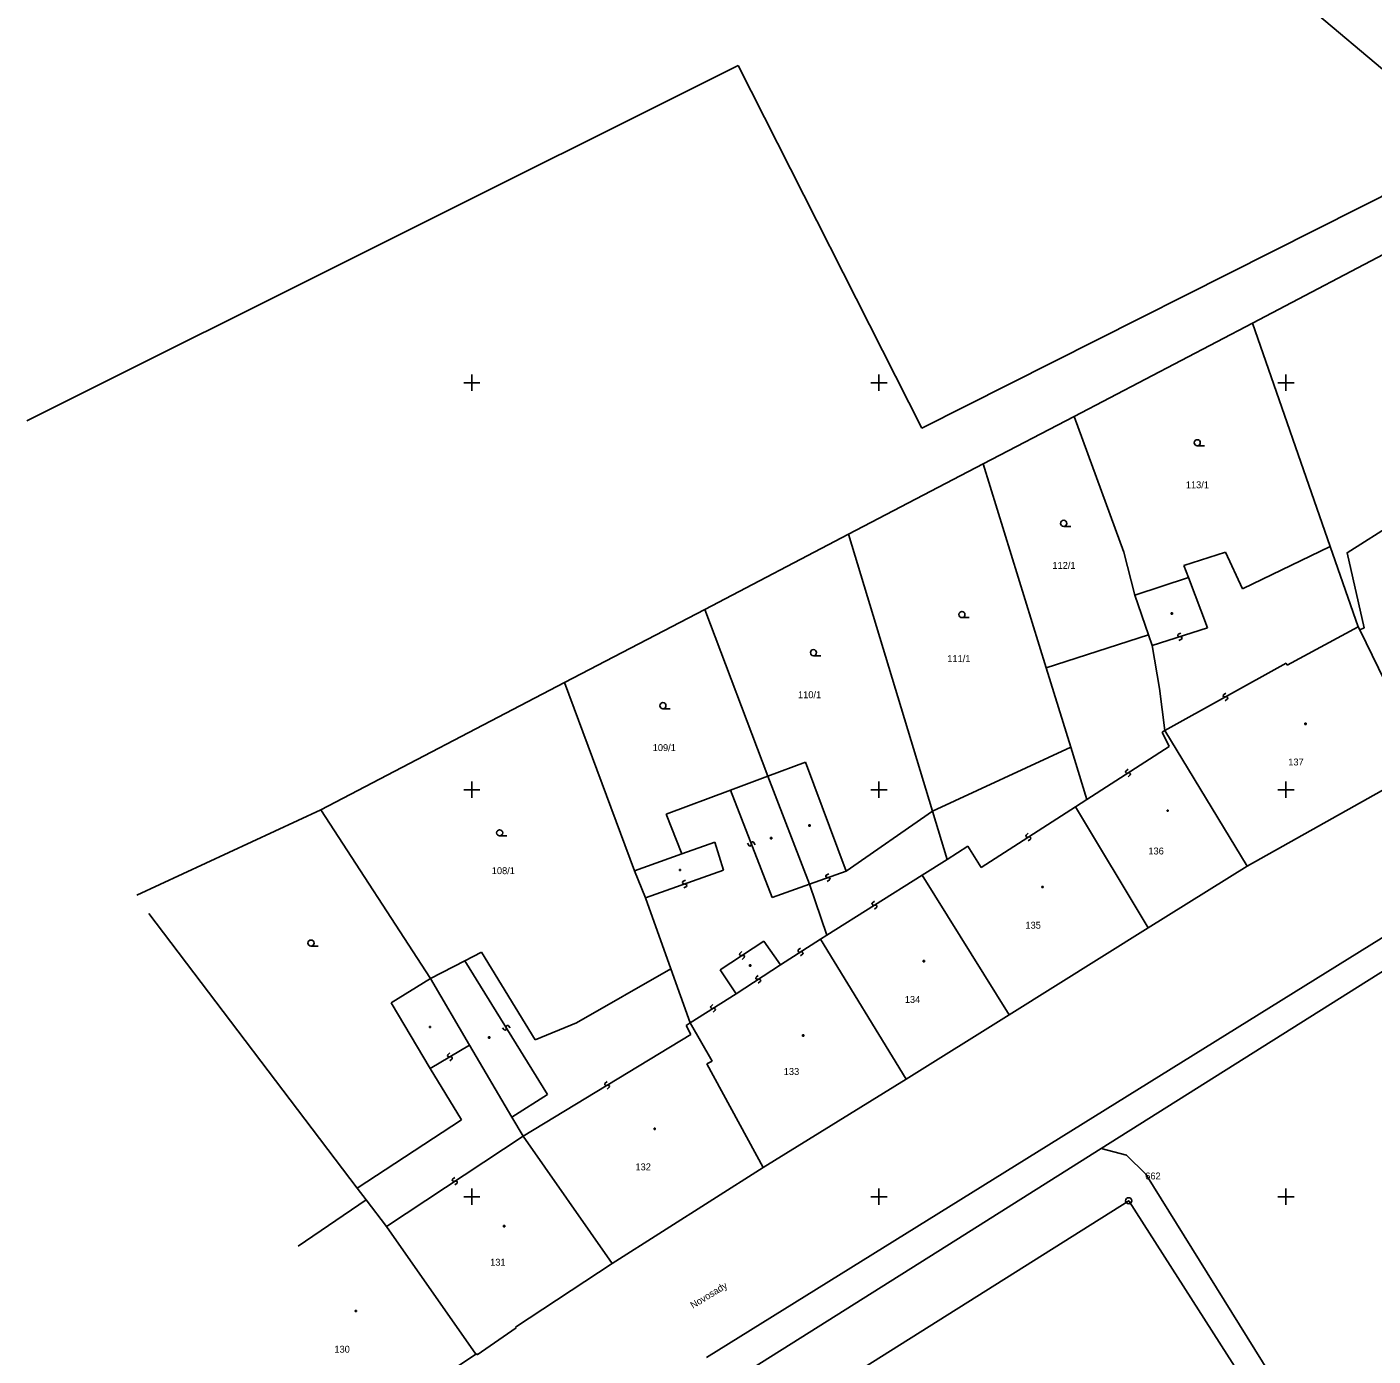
# Model space of a CAD drawing. Extents: x -492379 to -491966, y -1126153 to -1125860.
# Drawn here: x -492332.8 to -492233.6, y -1126091.7 to -1125993.8 of the extents above; entities that cross this region are included whole.
import ezdxf

# ---------------------------------------------------------------- set-up
doc = ezdxf.new("R2010")
doc.units = 0
doc.layers.add('katastrální mapa', color=7, linetype='Continuous')
doc.layers.add('síť', color=7, linetype='Continuous')

msp = doc.modelspace()

# ---------------------------------------------------------------- linework, layer by layer
at = {"layer": 'katastrální mapa'}
for p, q in [((-492225.94, -1126002.74), (-492307.13, -1125934.3)), ((-492332.79, -1126022.8), (-492280.36, -1125996.63)), ((-492280.36, -1125996.63), (-492266.84, -1126023.35)), ((-492266.84, -1126023.35), (-492225.94, -1126002.74)), ((-492242.46, -1126015.61), (-492228.24, -1126008.13)), ((-492255.61, -1126022.48), (-492242.46, -1126015.61)), ((-492242.46, -1126015.61), (-492236.73, -1126032.07)), ((-492262.32, -1126025.98), (-492255.61, -1126022.48)), ((-492255.61, -1126022.48), (-492251.95, -1126032.5)), ((-492246.54, -1126024.65), (-492246.01, -1126024.65)), ((-492272.25, -1126031.17), (-492262.32, -1126025.98)), ((-492262.32, -1126025.98), (-492257.67, -1126041.01)), ((-492282.84, -1126036.71), (-492272.25, -1126031.17)), ((-492272.25, -1126031.17), (-492266.05, -1126051.59)), ((-492256.38, -1126030.59), (-492255.85, -1126030.59)), ((-492243.2, -1126035.19), (-492236.73, -1126032.07)), ((-492236.73, -1126032.07), (-492234.67, -1126037.99)), ((-492251.95, -1126032.5), (-492251.14, -1126035.67)), ((-492247.52, -1126033.47), (-492244.45, -1126032.49)), ((-492244.45, -1126032.49), (-492243.2, -1126035.19)), ((-492251.14, -1126035.67), (-492247.18, -1126034.35)), ((-492247.52, -1126033.47), (-492247.18, -1126034.35)), ((-492247.18, -1126034.35), (-492245.78, -1126038.07)), ((-492251.14, -1126035.67), (-492250.14, -1126038.58)), ((-492293.17, -1126042.1), (-492282.84, -1126036.71)), ((-492282.84, -1126036.71), (-492278.18, -1126049.01)), ((-492263.88, -1126037.31), (-492263.35, -1126037.31)), ((-492248.45, -1126036.97), (-492248.36, -1126036.97)), ((-492248.45, -1126037.06), (-492248.45, -1126036.97)), ((-492248.36, -1126037.06), (-492248.45, -1126037.06)), ((-492248.36, -1126036.97), (-492248.36, -1126037.06)), ((-492249.86, -1126039.38), (-492245.78, -1126038.07)), ((-492239.9, -1126040.81), (-492234.67, -1126037.99)), ((-492234.67, -1126037.99), (-492234.56, -1126038.22)), ((-492234.56, -1126038.22), (-492230.32, -1126046.95)), ((-492257.67, -1126041.01), (-492250.14, -1126038.58)), ((-492250.14, -1126038.58), (-492249.86, -1126039.38)), ((-492249.86, -1126039.38), (-492249.31, -1126042.54)), ((-492247.94, -1126038.54), (-492247.98, -1126038.62)), ((-492247.98, -1126038.62), (-492247.96, -1126038.68)), ((-492247.96, -1126038.68), (-492247.89, -1126038.71)), ((-492247.75, -1126038.45), (-492247.94, -1126038.54)), ((-492247.89, -1126038.71), (-492247.75, -1126038.74)), ((-492247.7, -1126038.91), (-492247.89, -1126039)), ((-492247.75, -1126038.74), (-492247.68, -1126038.77)), ((-492247.66, -1126038.83), (-492247.7, -1126038.91)), ((-492247.68, -1126038.77), (-492247.66, -1126038.83)), ((-492274.82, -1126040.12), (-492274.29, -1126040.12)), ((-492257.67, -1126041.01), (-492255.86, -1126046.86)), ((-492248.92, -1126045.64), (-492239.99, -1126040.68)), ((-492239.99, -1126040.68), (-492239.9, -1126040.81)), ((-492311.14, -1126051.49), (-492293.17, -1126042.1)), ((-492293.17, -1126042.1), (-492288.01, -1126055.97)), ((-492249.31, -1126042.54), (-492248.92, -1126045.64)), ((-492244.61, -1126043.01), (-492244.63, -1126043.09)), ((-492244.63, -1126043.09), (-492244.6, -1126043.14)), ((-492244.44, -1126042.88), (-492244.61, -1126043.01)), ((-492244.6, -1126043.14), (-492244.52, -1126043.16)), ((-492244.52, -1126043.16), (-492244.39, -1126043.16)), ((-492244.3, -1126043.31), (-492244.47, -1126043.44)), ((-492244.39, -1126043.16), (-492244.31, -1126043.18)), ((-492244.31, -1126043.18), (-492244.28, -1126043.23)), ((-492244.28, -1126043.23), (-492244.3, -1126043.31)), ((-492285.92, -1126044.03), (-492285.39, -1126044.03)), ((-492238.6, -1126045.09), (-492238.51, -1126045.09)), ((-492238.6, -1126045.18), (-492238.6, -1126045.09)), ((-492238.51, -1126045.18), (-492238.6, -1126045.18)), ((-492238.51, -1126045.09), (-492238.51, -1126045.18)), ((-492249.13, -1126045.75), (-492248.92, -1126045.64)), ((-492249.13, -1126045.75), (-492248.61, -1126046.82)), ((-492248.92, -1126045.64), (-492242.87, -1126055.62)), ((-492266.05, -1126051.59), (-492255.86, -1126046.86)), ((-492255.86, -1126046.86), (-492254.67, -1126050.71)), ((-492254.67, -1126050.71), (-492248.61, -1126046.82)), ((-492278.18, -1126049.01), (-492275.42, -1126047.97)), ((-492275.42, -1126047.97), (-492272.4, -1126055.99)), ((-492242.87, -1126055.62), (-492229.69, -1126048.25)), ((-492280.94, -1126050.04), (-492278.18, -1126049.01)), ((-492278.18, -1126049.01), (-492275.11, -1126056.96)), ((-492251.8, -1126048.62), (-492251.82, -1126048.7)), ((-492251.82, -1126048.7), (-492251.79, -1126048.75)), ((-492251.64, -1126048.48), (-492251.8, -1126048.62)), ((-492251.79, -1126048.75), (-492251.71, -1126048.77)), ((-492251.71, -1126048.77), (-492251.57, -1126048.76)), ((-492251.48, -1126048.91), (-492251.64, -1126049.05)), ((-492251.57, -1126048.76), (-492251.49, -1126048.78)), ((-492251.49, -1126048.78), (-492251.46, -1126048.83)), ((-492251.46, -1126048.83), (-492251.48, -1126048.91)), ((-492285.68, -1126051.81), (-492280.94, -1126050.04)), ((-492280.94, -1126050.04), (-492277.86, -1126057.95)), ((-492262.47, -1126055.72), (-492255.51, -1126051.25)), ((-492255.51, -1126051.25), (-492254.67, -1126050.71)), ((-492255.51, -1126051.25), (-492250.16, -1126060.18)), ((-492324.68, -1126057.78), (-492311.14, -1126051.49)), ((-492311.14, -1126051.49), (-492303.04, -1126063.92)), ((-492285.68, -1126051.81), (-492284.53, -1126054.73)), ((-492272.4, -1126055.99), (-492266.05, -1126051.59)), ((-492266.05, -1126051.59), (-492264.98, -1126055.13)), ((-492248.76, -1126051.5), (-492248.67, -1126051.5)), ((-492248.76, -1126051.59), (-492248.76, -1126051.5)), ((-492248.67, -1126051.59), (-492248.76, -1126051.59)), ((-492248.67, -1126051.5), (-492248.67, -1126051.59)), ((-492275.16, -1126052.59), (-492275.07, -1126052.59)), ((-492275.16, -1126052.68), (-492275.16, -1126052.59)), ((-492275.07, -1126052.68), (-492275.16, -1126052.68)), ((-492275.07, -1126052.59), (-492275.07, -1126052.68)), ((-492258.99, -1126053.2), (-492259.15, -1126053.34)), ((-492297.95, -1126053.4), (-492297.42, -1126053.4)), ((-492284.53, -1126054.73), (-492282.1, -1126053.86)), ((-492282.1, -1126053.86), (-492281.44, -1126055.92)), ((-492279.57, -1126054.13), (-492279.68, -1126053.94)), ((-492279.5, -1126054.16), (-492279.57, -1126054.13)), ((-492279.44, -1126054.14), (-492279.5, -1126054.16)), ((-492279.41, -1126054.06), (-492279.44, -1126054.14)), ((-492279.39, -1126053.93), (-492279.41, -1126054.06)), ((-492279.36, -1126053.85), (-492279.39, -1126053.93)), ((-492279.3, -1126053.83), (-492279.36, -1126053.85)), ((-492279.23, -1126053.86), (-492279.3, -1126053.83)), ((-492279.12, -1126054.05), (-492279.23, -1126053.86)), ((-492277.98, -1126053.53), (-492277.89, -1126053.53)), ((-492277.98, -1126053.62), (-492277.98, -1126053.53)), ((-492277.89, -1126053.62), (-492277.98, -1126053.62)), ((-492277.89, -1126053.53), (-492277.89, -1126053.62)), ((-492264.98, -1126055.13), (-492263.45, -1126054.17)), ((-492263.45, -1126054.17), (-492262.47, -1126055.72)), ((-492259.15, -1126053.34), (-492259.17, -1126053.42)), ((-492259.17, -1126053.42), (-492259.14, -1126053.47)), ((-492259.14, -1126053.47), (-492259.06, -1126053.49)), ((-492259.06, -1126053.49), (-492258.92, -1126053.48)), ((-492258.83, -1126053.63), (-492258.99, -1126053.77)), ((-492258.92, -1126053.48), (-492258.84, -1126053.5)), ((-492258.84, -1126053.5), (-492258.81, -1126053.55)), ((-492258.81, -1126053.55), (-492258.83, -1126053.63)), ((-492288.01, -1126055.97), (-492284.53, -1126054.73)), ((-492266.81, -1126056.29), (-492264.98, -1126055.13)), ((-492288.01, -1126055.97), (-492287.2, -1126057.97)), ((-492287.2, -1126057.97), (-492281.44, -1126055.92)), ((-492284.7, -1126055.87), (-492284.61, -1126055.87)), ((-492284.7, -1126055.96), (-492284.7, -1126055.87)), ((-492284.61, -1126055.96), (-492284.7, -1126055.96)), ((-492284.61, -1126055.87), (-492284.61, -1126055.96)), ((-492275.11, -1126056.96), (-492272.4, -1126055.99)), ((-492273.69, -1126056.2), (-492273.88, -1126056.3)), ((-492250.16, -1126060.18), (-492242.87, -1126055.62)), ((-492284.45, -1126056.77), (-492284.48, -1126056.84)), ((-492284.48, -1126056.84), (-492284.46, -1126056.9)), ((-492284.46, -1126056.9), (-492284.39, -1126056.94)), ((-492284.26, -1126056.67), (-492284.45, -1126056.77)), ((-492284.39, -1126056.94), (-492284.25, -1126056.95)), ((-492284.19, -1126057.12), (-492284.38, -1126057.22)), ((-492284.25, -1126056.95), (-492284.18, -1126056.99)), ((-492284.16, -1126057.05), (-492284.19, -1126057.12)), ((-492284.18, -1126056.99), (-492284.16, -1126057.05)), ((-492282.7, -1126091.84), (-492226.15, -1126056.69)), ((-492277.86, -1126057.95), (-492275.11, -1126056.96)), ((-492275.11, -1126056.96), (-492273.84, -1126060.72)), ((-492273.88, -1126056.3), (-492273.92, -1126056.37)), ((-492273.92, -1126056.37), (-492273.9, -1126056.43)), ((-492273.9, -1126056.43), (-492273.82, -1126056.47)), ((-492273.84, -1126060.72), (-492266.81, -1126056.29)), ((-492273.82, -1126056.47), (-492273.69, -1126056.48)), ((-492273.63, -1126056.65), (-492273.82, -1126056.75)), ((-492273.69, -1126056.48), (-492273.61, -1126056.52)), ((-492273.59, -1126056.58), (-492273.63, -1126056.65)), ((-492273.61, -1126056.52), (-492273.59, -1126056.58)), ((-492266.81, -1126056.29), (-492260.41, -1126066.58)), ((-492257.98, -1126057.12), (-492257.89, -1126057.12)), ((-492257.98, -1126057.21), (-492257.98, -1126057.12)), ((-492257.89, -1126057.21), (-492257.98, -1126057.21)), ((-492257.89, -1126057.12), (-492257.89, -1126057.21)), ((-492287.2, -1126057.97), (-492285.34, -1126063.2)), ((-492270.33, -1126058.22), (-492270.49, -1126058.36)), ((-492323.81, -1126059.12), (-492308.44, -1126079.36)), ((-492270.49, -1126058.36), (-492270.51, -1126058.44)), ((-492270.51, -1126058.44), (-492270.47, -1126058.49)), ((-492270.47, -1126058.49), (-492270.39, -1126058.51)), ((-492270.39, -1126058.51), (-492270.26, -1126058.5)), ((-492270.16, -1126058.65), (-492270.32, -1126058.79)), ((-492270.26, -1126058.5), (-492270.18, -1126058.52)), ((-492270.18, -1126058.52), (-492270.14, -1126058.57)), ((-492270.14, -1126058.57), (-492270.16, -1126058.65)), ((-492260.41, -1126066.58), (-492250.16, -1126060.18)), ((-492281.69, -1126063.28), (-492278.48, -1126061.15)), ((-492278.48, -1126061.15), (-492277.25, -1126062.9)), ((-492277.25, -1126062.9), (-492274.3, -1126061.01)), ((-492274.3, -1126061.01), (-492273.84, -1126060.72)), ((-492274.3, -1126061.01), (-492268, -1126071.33)), ((-492311.85, -1126061.53), (-492311.32, -1126061.53)), ((-492300.51, -1126062.61), (-492299.29, -1126061.97)), ((-492299.29, -1126061.97), (-492295.33, -1126068.44)), ((-492280.25, -1126062.07), (-492280.27, -1126062.16)), ((-492280.27, -1126062.16), (-492280.23, -1126062.21)), ((-492280.09, -1126061.93), (-492280.25, -1126062.07)), ((-492280.23, -1126062.21), (-492280.15, -1126062.22)), ((-492280.15, -1126062.22), (-492280.02, -1126062.21)), ((-492280.02, -1126062.21), (-492279.94, -1126062.22)), ((-492279.94, -1126062.22), (-492279.9, -1126062.27)), ((-492275.94, -1126061.81), (-492275.96, -1126061.89)), ((-492275.96, -1126061.89), (-492275.92, -1126061.94)), ((-492275.78, -1126061.67), (-492275.94, -1126061.81)), ((-492275.92, -1126061.94), (-492275.84, -1126061.96)), ((-492275.84, -1126061.96), (-492275.71, -1126061.95)), ((-492275.61, -1126062.1), (-492275.77, -1126062.24)), ((-492275.71, -1126061.95), (-492275.63, -1126061.97)), ((-492275.63, -1126061.97), (-492275.59, -1126062.02)), ((-492275.59, -1126062.02), (-492275.61, -1126062.1)), ((-492303.04, -1126063.92), (-492300.51, -1126062.61)), ((-492300.51, -1126062.61), (-492294.42, -1126072.47)), ((-492292.29, -1126067.18), (-492285.34, -1126063.2)), ((-492285.34, -1126063.2), (-492283.92, -1126067.19)), ((-492280.53, -1126065.03), (-492277.25, -1126062.9)), ((-492279.92, -1126062.36), (-492280.08, -1126062.5)), ((-492279.9, -1126062.27), (-492279.92, -1126062.36)), ((-492279.54, -1126062.91), (-492279.45, -1126062.91)), ((-492279.54, -1126063), (-492279.54, -1126062.91)), ((-492279.45, -1126063), (-492279.54, -1126063)), ((-492279.45, -1126062.91), (-492279.45, -1126063)), ((-492266.73, -1126062.59), (-492266.64, -1126062.59)), ((-492266.73, -1126062.68), (-492266.73, -1126062.59)), ((-492266.64, -1126062.68), (-492266.73, -1126062.68)), ((-492266.64, -1126062.59), (-492266.64, -1126062.68)), ((-492253.63, -1126076.45), (-492231.88, -1126062.75)), ((-492305.94, -1126065.7), (-492303.04, -1126063.92)), ((-492303.04, -1126063.92), (-492300.16, -1126068.83)), ((-492281.69, -1126063.28), (-492280.53, -1126065.03)), ((-492279.05, -1126063.82), (-492279.07, -1126063.9)), ((-492279.07, -1126063.9), (-492279.04, -1126063.95)), ((-492278.89, -1126063.68), (-492279.05, -1126063.82)), ((-492279.04, -1126063.95), (-492278.96, -1126063.97)), ((-492278.96, -1126063.97), (-492278.82, -1126063.96)), ((-492278.73, -1126064.11), (-492278.89, -1126064.25)), ((-492278.82, -1126063.96), (-492278.74, -1126063.98)), ((-492278.74, -1126063.98), (-492278.71, -1126064.03)), ((-492278.71, -1126064.03), (-492278.73, -1126064.11)), ((-492283.92, -1126067.19), (-492280.53, -1126065.03)), ((-492305.94, -1126065.7), (-492303.07, -1126070.54)), ((-492282.39, -1126065.97), (-492282.41, -1126066.05)), ((-492282.41, -1126066.05), (-492282.37, -1126066.1)), ((-492282.23, -1126065.83), (-492282.39, -1126065.97)), ((-492282.37, -1126066.1), (-492282.29, -1126066.12)), ((-492282.29, -1126066.12), (-492282.16, -1126066.1)), ((-492282.16, -1126066.1), (-492282.08, -1126066.12)), ((-492282.08, -1126066.12), (-492282.04, -1126066.17)), ((-492282.04, -1126066.17), (-492282.06, -1126066.25)), ((-492295.33, -1126068.44), (-492292.29, -1126067.18)), ((-492282.06, -1126066.25), (-492282.22, -1126066.39)), ((-492268, -1126071.33), (-492260.41, -1126066.58)), ((-492303.13, -1126067.44), (-492303.04, -1126067.44)), ((-492303.13, -1126067.53), (-492303.13, -1126067.44)), ((-492303.04, -1126067.53), (-492303.13, -1126067.53)), ((-492303.04, -1126067.44), (-492303.04, -1126067.53)), ((-492297.61, -1126067.7), (-492297.75, -1126067.54)), ((-492297.53, -1126067.72), (-492297.61, -1126067.7)), ((-492297.48, -1126067.69), (-492297.53, -1126067.72)), ((-492297.46, -1126067.61), (-492297.48, -1126067.69)), ((-492297.45, -1126067.39), (-492297.47, -1126067.47)), ((-492297.47, -1126067.47), (-492297.46, -1126067.61)), ((-492297.4, -1126067.36), (-492297.45, -1126067.39)), ((-492297.32, -1126067.38), (-492297.4, -1126067.36)), ((-492297.18, -1126067.54), (-492297.32, -1126067.38)), ((-492296.21, -1126075.52), (-492283.85, -1126068.05)), ((-492284.21, -1126067.38), (-492283.92, -1126067.19)), ((-492284.21, -1126067.38), (-492283.85, -1126068.05)), ((-492283.92, -1126067.19), (-492282.28, -1126070)), ((-492275.63, -1126068.06), (-492275.54, -1126068.06)), ((-492275.63, -1126068.15), (-492275.63, -1126068.06)), ((-492275.54, -1126068.15), (-492275.63, -1126068.15)), ((-492275.54, -1126068.06), (-492275.54, -1126068.15)), ((-492303.07, -1126070.54), (-492300.16, -1126068.83)), ((-492300.16, -1126068.83), (-492297.05, -1126074.14)), ((-492298.76, -1126068.22), (-492298.67, -1126068.22)), ((-492298.76, -1126068.31), (-492298.76, -1126068.22)), ((-492298.67, -1126068.31), (-492298.76, -1126068.31)), ((-492298.67, -1126068.22), (-492298.67, -1126068.31)), ((-492301.77, -1126069.53), (-492301.79, -1126069.62)), ((-492301.79, -1126069.62), (-492301.76, -1126069.67)), ((-492301.61, -1126069.4), (-492301.77, -1126069.53)), ((-492301.76, -1126069.67), (-492301.68, -1126069.69)), ((-492301.68, -1126069.69), (-492301.55, -1126069.68)), ((-492301.46, -1126069.84), (-492301.62, -1126069.97)), ((-492301.55, -1126069.68), (-492301.47, -1126069.7)), ((-492301.47, -1126069.7), (-492301.44, -1126069.75)), ((-492301.44, -1126069.75), (-492301.46, -1126069.84)), ((-492282.68, -1126070.21), (-492282.28, -1126070)), ((-492303.07, -1126070.54), (-492300.76, -1126074.33)), ((-492282.68, -1126070.21), (-492278.54, -1126077.83)), ((-492290.19, -1126071.64), (-492290.21, -1126071.72)), ((-492290.21, -1126071.72), (-492290.18, -1126071.77)), ((-492290.03, -1126071.5), (-492290.19, -1126071.64)), ((-492290.18, -1126071.77), (-492290.1, -1126071.79)), ((-492290.1, -1126071.79), (-492289.96, -1126071.78)), ((-492289.87, -1126071.93), (-492290.03, -1126072.07)), ((-492289.96, -1126071.78), (-492289.88, -1126071.8)), ((-492289.88, -1126071.8), (-492289.85, -1126071.85)), ((-492289.85, -1126071.85), (-492289.87, -1126071.93)), ((-492278.54, -1126077.83), (-492268, -1126071.33)), ((-492297.05, -1126074.14), (-492294.42, -1126072.47)), ((-492308.44, -1126079.36), (-492300.76, -1126074.33)), ((-492297.05, -1126074.14), (-492296.21, -1126075.52)), ((-492286.57, -1126074.94), (-492286.48, -1126074.94)), ((-492286.57, -1126075.03), (-492286.57, -1126074.94)), ((-492286.48, -1126075.03), (-492286.57, -1126075.03)), ((-492286.48, -1126074.94), (-492286.48, -1126075.03)), ((-492306.3, -1126082.18), (-492296.21, -1126075.52)), ((-492296.21, -1126075.52), (-492289.65, -1126084.92)), ((-492264.32, -1126083.19), (-492253.63, -1126076.45)), ((-492253.63, -1126076.45), (-492251.75, -1126076.93)), ((-492251.75, -1126076.93), (-492250.32, -1126078.33)), ((-492289.65, -1126084.92), (-492278.54, -1126077.83)), ((-492301.42, -1126078.71), (-492301.44, -1126078.79)), ((-492301.44, -1126078.79), (-492301.4, -1126078.84)), ((-492301.26, -1126078.57), (-492301.42, -1126078.71)), ((-492301.4, -1126078.84), (-492301.32, -1126078.86)), ((-492301.32, -1126078.86), (-492301.19, -1126078.84)), ((-492301.09, -1126078.99), (-492301.25, -1126079.13)), ((-492301.19, -1126078.84), (-492301.11, -1126078.86)), ((-492301.11, -1126078.86), (-492301.07, -1126078.91)), ((-492301.07, -1126078.91), (-492301.09, -1126078.99)), ((-492250.32, -1126078.33), (-492233.77, -1126104.94)), ((-492308.44, -1126079.36), (-492307.78, -1126080.23)), ((-492312.81, -1126083.64), (-492307.78, -1126080.23)), ((-492307.78, -1126080.23), (-492306.3, -1126082.18)), ((-492273.82, -1126094.29), (-492251.59, -1126080.29)), ((-492251.59, -1126080.29), (-492238.38, -1126100.91)), ((-492306.3, -1126082.18), (-492299.71, -1126091.6)), ((-492297.66, -1126082.12), (-492297.57, -1126082.12)), ((-492297.66, -1126082.21), (-492297.66, -1126082.12)), ((-492297.57, -1126082.21), (-492297.66, -1126082.21)), ((-492297.57, -1126082.12), (-492297.57, -1126082.21)), ((-492281.31, -1126093.89), (-492264.32, -1126083.19)), ((-492296.78, -1126089.6), (-492289.65, -1126084.92)), ((-492308.6, -1126088.37), (-492308.51, -1126088.37)), ((-492308.6, -1126088.46), (-492308.6, -1126088.37)), ((-492308.51, -1126088.46), (-492308.6, -1126088.46)), ((-492308.51, -1126088.37), (-492308.51, -1126088.46)), ((-492299.6, -1126091.64), (-492296.73, -1126089.67)), ((-492296.78, -1126089.6), (-492296.73, -1126089.67)), ((-492311.11, -1126099.22), (-492299.71, -1126091.6)), ((-492299.71, -1126091.6), (-492299.66, -1126091.56)), ((-492299.66, -1126091.56), (-492299.6, -1126091.64))]:
    msp.add_line(p, q, dxfattribs=at)
msp.add_lwpolyline([(-492216.62, -1126038.36), (-492224.43, -1126025.6), (-492229.32, -1126028.67), (-492230.16, -1126027.37), (-492232.71, -1126028.97), (-492231.93, -1126030.27), (-492235.49, -1126032.53), (-492234.24, -1126038.07), (-492234.56, -1126038.22)], dxfattribs=at)
for centre, radius in [((-492246.54, -1126024.425), 0.225), ((-492256.38, -1126030.365), 0.225), ((-492263.88, -1126037.085), 0.225), ((-492274.82, -1126039.895), 0.225), ((-492285.92, -1126043.805), 0.225), ((-492297.95, -1126053.175), 0.225), ((-492311.85, -1126061.305), 0.225), ((-492251.59, -1126080.29), 0.225), ((-492251.59, -1126080.29), 0.003)]:
    msp.add_circle(centre, radius, dxfattribs=at)
at = {"layer": 'síť'}
for p, q in [((-492300, -1126019.4), (-492300, -1126020.6)), ((-492270, -1126019.4), (-492270, -1126020.6)), ((-492240, -1126019.4), (-492240, -1126020.6)), ((-492300.6, -1126020), (-492299.4, -1126020)), ((-492270.6, -1126020), (-492269.4, -1126020)), ((-492240.6, -1126020), (-492239.4, -1126020)), ((-492300.6, -1126050), (-492299.4, -1126050)), ((-492300, -1126049.4), (-492300, -1126050.6)), ((-492270.6, -1126050), (-492269.4, -1126050)), ((-492270, -1126049.4), (-492270, -1126050.6)), ((-492240.6, -1126050), (-492239.4, -1126050)), ((-492240, -1126049.4), (-492240, -1126050.6)), ((-492300.6, -1126080), (-492299.4, -1126080)), ((-492300, -1126079.4), (-492300, -1126080.6)), ((-492270.6, -1126080), (-492269.4, -1126080)), ((-492270, -1126079.4), (-492270, -1126080.6)), ((-492240.6, -1126080), (-492239.4, -1126080)), ((-492240, -1126079.4), (-492240, -1126080.6))]:
    msp.add_line(p, q, dxfattribs=at)

# ---------------------------------------------------------------- texts
at = {"layer": 'katastrální mapa'}
for s, p in [('113/1', (-492247.38, -1126027.78)), ('112/1', (-492257.21, -1126033.72)), ('111/1', (-492264.96, -1126040.59)), ('110/1', (-492275.96, -1126043.25)), ('109/1', (-492286.67, -1126047.15)), ('137', (-492239.83, -1126048.21)), ('136', (-492250.14, -1126054.77)), ('108/1', (-492298.53, -1126056.22)), ('135', (-492259.2, -1126060.24)), ('134', (-492268.09, -1126065.71)), ('133', (-492277.01, -1126071.02)), ('132', (-492287.94, -1126078.05)), ('662', (-492250.37, -1126078.72)), ('131', (-492298.65, -1126085.08)), ('130', (-492310.13, -1126091.49))]:
    msp.add_text(s, height=0.51, dxfattribs=at).set_placement(p)
msp.add_text('Novosady', height=0.51, rotation=31.572, dxfattribs=at).set_placement((-492283.7, -1126088.26))

doc.saveas('drawing.dxf')
